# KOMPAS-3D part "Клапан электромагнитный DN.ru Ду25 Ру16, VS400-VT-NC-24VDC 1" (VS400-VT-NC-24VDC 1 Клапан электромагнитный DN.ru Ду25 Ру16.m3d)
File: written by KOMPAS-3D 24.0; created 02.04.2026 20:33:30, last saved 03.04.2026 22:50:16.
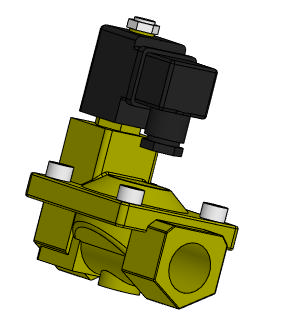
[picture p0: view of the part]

Document properties: Автор: artio; Полное имя файла: C:\Users\artio\OneDrive\Рабочий стол\Клапан электромагнитный DN.ru\VS400-VT-NC\VS400-VT-NC-24VDC 1 Клапан электромагнитный DN.ru Ду25 Ру16.m3d

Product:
- Body: Тело 1  | qty 1
    Масса: 1.76797
- Part/product: Клапан электромагнитный DN.ru Ду25 Ру16  | designation VS400-VT-NC-24VDC 1
    Масса: 1.524
    Раздел спецификации: Прочие изделия
    Примечание: D130-04735
    additional columns: ef56311e-7521-43dc-8291-0e6108b3d81d; VS400-ET-NC-220VAC 1; artio; c; Шероховатость не задана; Да

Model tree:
1. Операция без истории:1

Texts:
  VS400-VT-NC-24VDC 1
